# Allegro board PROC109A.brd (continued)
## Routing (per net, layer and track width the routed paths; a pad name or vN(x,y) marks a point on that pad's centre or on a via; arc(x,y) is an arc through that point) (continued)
TEST_LED4_GREEN: length 184.3
  TOP w0.102: v2(79.85,-47.86) 79.81,-47.81 U18.F3
  L03_SIG1 w0.121: v1(169.57,-12.28) 172.4,-12.28 173.27,-13.14 173.27,-15.1 170.87,-17.5 168.45,-17.5 157.63,-28.32 157.63,-52.83 157.8,-53 157.8,-55.25 156.21,-56.85 144.72,-56.85 142.85,-58.71 140.17,-58.71 138.28,-56.82 132.26,-56.82 131.44,-56 125.55,-56 125.16,-56.39 116.02,-56.39 115.95,-56.33 v1(115.87,-56.33) 115.56,-56.01 106.65,-56.01 106.61,-55.98 97.99,-55.98 96.83,-57.15 89.21,-57.15 89.04,-57.31 81.98,-57.31 81.33,-56.67 79.76,-56.67 78.89,-55.8 78.89,-51.89 79.04,-51.74 79.04,-48.66 v2(79.85,-47.86)
  BOTTOM w0.135: v1(115.87,-56.33) 115.87,-55.63 114.35,-54.1 114.35,-36.7 111.76,-34.11 111.76,-25.98 111.76,-25.96 111.77,-25.94 112.29,-25.43 113.67,-25.43 114.68,-24.41 U51.11 ; Q4.3 170.24,-12.51 170.02,-12.28 v1(169.57,-12.28) 168.77,-12.28 R165.2
TIMER_IO0: length 91.3
  TOP w0.102: v2(81.84,-40.35) 81.81,-40.32 U18.K18
  L03_SIG1 w0.121: v1(79.91,-26.54) 82.35,-28.98 82.35,-35.44 82.01,-35.78 82.01,-40.18 v2(81.84,-40.35) ; v1(91.1,-24.95) 91.08,-24.95 90.96,-24.83 90.96,-24.82 90.93,-24.79 90.93,-24.51 91.64,-23.8 93.83,-23.8 94.39,-24.36 94.95,-24.36 95.3,-24 95.99,-24 96.1,-24.11 96.45,-24.11 96.56,-24 v1(101.27,-24)
  BOTTOM w0.135: v1(101.27,-24) 101.35,-24.08 101.35,-24.51 102.54,-25.71 102.54,-27.05 103.11,-27.62 103.36,-27.62 103.78,-28.04 103.78,-28.73 97.38,-35.13 97.38,-36.81 96.77,-37.41 94.35,-37.41 93.66,-38.11 93.66,-39.91 94.12,-40.37 95.38,-41.63 95.38,-51.57 95.81,-52 95.81,-59.32 95.93,-59.45 95.93,-60.76 94.61,-62.08 92.13,-62.08 91.42,-61.38 U50.12 ; 90.1,-25.33 R193.1 ; 90.1,-25.33 88.3,-25.33 87.93,-24.97 87.58,-24.97 86.56,-23.95 82.5,-23.95 v1(79.91,-26.54) ; 90.1,-25.33 90.72,-25.33 v1(91.1,-24.95)
TIMER_IO0/EHPWM3_B: length 56.4
  TOP w0.135: v1(101.19,-19.15) 102.31,-18.03 J6.1
  BOTTOM w0.135: v1(101.19,-19.15) 100.8,-19.54 100.8,-24.35 102.04,-25.59 102.04,-26.93 103,-27.89 103.25,-27.89 103.5,-28.14 103.5,-28.63 97.43,-34.7 96.08,-34.7 93.12,-37.66 93.12,-40.14 94.81,-41.82 94.81,-51.76 95.25,-52.21 95.25,-59.53 95.39,-59.67 95.39,-60.33 94.35,-61.38 92.39,-61.38 92.22,-61.22 U50.10
TIMER_IO1: length 55.9
  TOP w0.102: 81.36,-37.97 81.39,-38 81.39,-39.03 81.39,-39.04 U18.K20
  TOP w0.135: v1(78.71,-28.68) 81.74,-31.7 81.74,-34.01 80.95,-34.8 80.95,-35.36 81.36,-35.77 81.36,-37.97 ; R19.1 89.51,-23.47 v1(89.51,-22.4)
  L03_SIG1 w0.121: v1(108.89,-20.83) 107.57,-22.15 102.83,-22.15 102.02,-22.96 101.67,-22.96 100.86,-22.15 97.15,-22.15 97.13,-22.13 95.97,-22.13 95.95,-22.15 93.29,-22.15 92.62,-22.83 89.93,-22.83 v1(89.51,-22.4)
  BOTTOM w0.135: v1(89.51,-22.4) 89.42,-22.31 82.72,-22.31 78.05,-26.97 78.05,-28.02 v1(78.71,-28.68) ; U51.16 113.68,-21.78 113.05,-21.15 109.21,-21.15 v1(108.89,-20.83)
TIMER_IO1/EHPWM5_A: length 11.3
  BOTTOM w0.135: J6.3 106.79,-19.22 106.79,-19.23 106.79,-19.39 107.44,-20.04 107.44,-20.32 107.76,-20.63 108.09,-20.63 108.6,-20.13 109.18,-20.13 109.39,-20.34 113.41,-20.34 114.68,-21.61 U51.2
TIMER_IO2: length 61.8
  TOP w0.102: v2(81.46,-39.76) 81.4,-39.82 U18.J19
  TOP w0.135: v1(107.87,-20.14) 107.87,-20.59 107.43,-21.03 106.65,-21.03 106.17,-20.55 101.22,-20.55 100.86,-20.9 100.86,-20.93 100.53,-21.26 92.1,-21.26 91.76,-21.6 91.76,-25.44 v1(92.08,-25.76)
  L03_SIG1 w0.121: v2(81.46,-39.76) 81.75,-39.47 81.75,-35.68 82.09,-35.34 82.09,-29.31 79.93,-27.15 v1(78.92,-27.15)
  BOTTOM w0.135: R192.1 92.1,-25.25 92.08,-25.27 v1(92.08,-25.76) 88.34,-25.76 87.83,-25.25 87.48,-25.25 87.31,-25.08 86.49,-24.26 83.08,-24.26 80.19,-27.15 v1(78.92,-27.15) ; U51.3 115.08,-21.46 113.69,-20.07 109.5,-20.07 109.29,-19.86 108.16,-19.86 v1(107.87,-20.14)
TIMER_IO2/EHPWM8_B: length 10
  BOTTOM w0.135: U51.5 116.08,-20.58 115.23,-19.73 110.32,-19.73 110.18,-19.59 110.18,-18.89 J6.5
TIMER_IO3: length 70.4
  TOP w0.102: v2(80.33,-39.78) 80.59,-40.03 80.61,-40.03 U18.J18
  L03_SIG1 w0.102: v2(80.33,-39.78) 80.33,-38.15 80.51,-37.97
  L03_SIG1 w0.121: v1(116.54,-19.94) 116.23,-19.94 116.13,-19.84 110.82,-19.84 108.25,-22.41 102.94,-22.41 102.13,-23.21 101.57,-23.21 101.17,-22.82 99.69,-22.82 99.49,-23.01 95.57,-23.01 95.01,-23.57 94.34,-23.57 v1(93.45,-22.68) ; 80.51,-37.97 80.51,-35.88 80.41,-35.78 80.41,-34.58 81.07,-33.92 81.07,-33.39 79.98,-32.31 78.61,-32.31 78.16,-31.85 78.16,-29.64 78.56,-29.24 79.45,-29.24 79.78,-28.91 v1(79.78,-28.12)
  BOTTOM w0.135: 86.06,-22.83 v1(87.27,-24.05) 87.92,-24.7 88.05,-24.7 R194.1 ; 86.06,-22.83 87.22,-22.83 87.48,-22.58 89.08,-22.58 89.54,-23.04 93.09,-23.04 v1(93.45,-22.68) ; 86.06,-22.83 82.63,-22.83 78.49,-26.97 78.49,-27.56 79.04,-28.12 v1(79.78,-28.12) ; U51.9 115.48,-23.99 115.78,-24.28 116.53,-24.28 116.77,-24.05 116.95,-24.05 117.2,-23.8 117.2,-23.42 117.07,-23.29 117.07,-20.47 v1(116.54,-19.94)
TIMER_IO3/EHPWM8_A: length 9.8
  BOTTOM w0.135: U51.7 116.42,-23.19 116.45,-23.16 116.69,-23.16 116.79,-23.06 116.79,-20.8 115.44,-19.46 112.08,-19.46 111.87,-19.24 J6.7
TIMER_IO4: length 29
  TOP w0.135: v1(90.93,-21.62) 90.94,-21.62 R20.1
  L03_SIG1 w0.121: v1(105.66,-20.98) 105.22,-20.98 105.15,-21.06 103.17,-21.06 102.62,-21.62 102.25,-21.62 102.23,-21.6 101.46,-21.6 101.45,-21.62 v1(90.93,-21.62)
  BOTTOM w0.135: U51.12 114.28,-24.3 113.64,-24.94 111.24,-24.94 110.52,-24.23 110.52,-22.06 110.13,-21.67 106.35,-21.67 v1(105.66,-20.98)
TIMER_IO4/EHPWM7_B: length 11.1
  BOTTOM w0.135: U51.10 115.08,-24.45 115.22,-24.59 116.64,-24.59 116.75,-24.45 116.88,-24.32 117.06,-24.32 117.59,-23.79 117.59,-20.38 116.46,-19.25 115.62,-19.25 J6.9
TIMER_IO4_R: length 30.5
  TOP w0.102: U18.J20 81.17,-39.04 81.17,-38.43 81,-38.25 81,-37.97
  TOP w0.135: 81,-37.97 81,-35.84 80.68,-35.52 80.68,-34.66 81.47,-33.87 81.47,-32.08 v1(79.04,-29.66) ; v1(86.28,-24.82) 86.28,-24.23 86.94,-23.57 87.55,-23.57 88.82,-24.84 90.32,-24.84 90.9,-24.26 R20.2
  BOTTOM w0.135: v1(79.04,-29.66) 85.56,-29.66 86.11,-29.11 86.11,-27.7 85.19,-26.79 85.19,-25.07 85.45,-24.82 v1(86.28,-24.82)
TIMER_IO5: length 118.4
  TOP w0.102: 80.7,-37.97 80.7,-38.56 80.7,-38.62 U18.J21
  TOP w0.135: v1(92.43,-22.4) 92.43,-23.47 R21.1 ; v1(77.19,-27.94) 77.19,-28.45 79.25,-30.51 79.48,-30.51 81.15,-32.18 81.15,-33.73 80.41,-34.47 80.41,-35.78 80.7,-36.07 80.7,-37.97
  L03_SIG1 w0.121: v1(120.52,-20.17) 119.87,-19.52 118.62,-19.52 118.41,-19.73 118.06,-19.73 117.85,-19.52 110.63,-19.52 109.6,-20.55 109.21,-20.55 109.07,-20.4 108.37,-20.4 106.88,-21.89 97.25,-21.89 97.23,-21.88 92.95,-21.88 v1(92.43,-22.4)
  BOTTOM w0.135: v1(92.43,-22.4) 90.96,-22.4 90.24,-21.69 89.8,-21.69 89.51,-21.97 82.62,-21.97 77.19,-27.41 v1(77.19,-27.94) ; v1(120.52,-20.17) 120.84,-20.48 120.84,-20.87 ; 120.85,-20.85 120.84,-20.87 ; 120.84,-20.87 120.53,-21.17 120.53,-23.3 120.62,-23.39 120.62,-26.76 120.76,-26.9 122.5,-26.9 122.76,-27.15 122.76,-27.63 125.56,-30.44 129.58,-30.44 130.31,-31.17 130.31,-38.24 130.31,-40.89 129.84,-41.36 129.84,-50.53 124.41,-55.96 119.96,-55.96 119.48,-55.47 117.86,-55.47 117.51,-55.13 117.51,-54.8 v1(117.2,-54.48) 117.2,-54.17 117.6,-53.77 117.8,-53.77 118.09,-53.47 U52.16
TIMER_IO5/EHPWM7_A: length 50.3
  TOP w0.135: J6.11 116.95,-19.24 117.44,-19.74 121.03,-19.74 123.38,-22.09 123.38,-27.7 120.42,-30.66 120.42,-32.59 120.67,-32.84 121.04,-32.84 122.87,-34.67 124.2,-34.67 125.93,-36.4 125.94,-36.41 125.94,-36.43 125.94,-36.97 125.94,-36.99 125.93,-37.01 125.67,-37.26 125.67,-38.42 125.35,-38.76 125.35,-40.56 125.29,-40.62 124.84,-41.07 124.84,-45.43 124.28,-45.99 124.28,-48.77 123.01,-50.04 121.39,-50.04 119.04,-52.39 v1(117.06,-52.39)
  BOTTOM w0.135: U52.2 117.17,-52.27 v1(117.06,-52.39)
TM4C129_TCK: length 5.1
  TOP w0.135: v1(24.43,-33.96) 24.53,-34.06 TP18.1
  BOTTOM w0.135: U37.100 21.9,-32.34 23.53,-33.96 v1(24.43,-33.96)
TM4C129_TDI: length 3.8
  TOP w0.135: TP16.1 21.77,-34.78 v1(21.77,-33.96)
  BOTTOM w0.135: U37.98 21.1,-33.3 v1(21.77,-33.96)
TM4C129_TDO: length 3.6
  TOP w0.135: v1(20.62,-32.97) 20.42,-33.18 TP15.1
  BOTTOM w0.135: U37.97 20.7,-32.89 v1(20.62,-32.97)
TM4C129_TMS: length 4.2
  TOP w0.135: TP17.1 23.16,-34.36 v1(22.91,-34.11)
  BOTTOM w0.135: v1(22.91,-34.11) 21.5,-32.7 U37.99
TUSB_ADDR: length 3.9
  TOP w0.135: U20.5 13.55,-46.09 13.87,-45.77 TP29.1
TUSB_ID: length 3.9
  TOP w0.135: TP28.1 9.02,-44.88 9.64,-44.88 10.45,-45.69 U20.9
TUSB_INT_N: length 2
  TOP w0.135: R110.1 14.14,-45 13.45,-45.69 U20.6
TUSB_OUT1: length 5.6
  TOP w0.135: R107.1 13.79,-42.11 13.26,-41.58 12.83,-41.58 12.27,-41.02 12.27,-39.42 12.57,-39.12 U15.2
TUSB_OUT1_R: length 3.5
  TOP w0.135: R107.2 R106.1 12.34,-44.3 11.92,-44.72 U20.7
TUSB_OUT2: length 7.3
  TOP w0.135: U15.1 12.63,-38.62 12.37,-38.35 R92.2 11.67,-39.97 9.45,-42.19 R104.1
TUSB_OUT2_R: length 3.6
  TOP w0.135: R104.2 R105.1 10.9,-44.39 11.52,-45.01 U20.8
TYPEC_CC1: length 15
  TOP w0.135: v1(13.46,-54.08) 11.52,-52.14 U20.1
  TOP w0.254: v1(17.78,-56.01) 17.77,-56.02 J10.A5
  L03_SIG1 w0.127: v1(13.46,-54.08) 13.46,-54.99 15.04,-56.57 17.22,-56.57 v1(17.78,-56.01)
TYPEC_CC2: length 18.9
  TOP w0.135: v1(13.51,-52.96) 11.92,-51.37 U20.2
  L03_SIG1 w0.127: J10.B5 18.46,-59.79 16.13,-59.79 12.55,-56.21 12.55,-53.92 v1(13.51,-52.96)
TYPEC_DN: length 15.3
  TOP w0.107: J10.A7 18.77,-56.16 18.64,-56.03 18.64,-55.48 v1(19,-55.12)
  L03_SIG1 w0.102: J10.B7 18.4,-57.95 18.4,-57.72 20.17,-55.95 20.17,-54.48 19.38,-53.7 18.9,-53.7 18.57,-54.03 18.57,-55.32 18.67,-55.42 18.88,-55.42 19,-55.3 v1(19,-55.12)
  BOTTOM w0.107: v1(19,-55.12) 18.7,-54.81 18.7,-54.59 18.09,-53.98 18.09,-53.64 18.32,-53.41 D6.1 18.32,-52.92 18.09,-52.69 18.09,-52.2 18.4,-51.89 L3.2
TYPEC_DP: length 15.3
  TOP w0.107: J10.A6 18.27,-56.16 18.4,-56.03 18.4,-55.46 v1(18.06,-55.12)
  L03_SIG1 w0.102: J10.B6 18.66,-57.97 18.66,-57.82 20.42,-56.06 20.42,-54.38 19.49,-53.44 18.8,-53.44 18.31,-53.92 18.31,-54.87 v1(18.06,-55.12)
  BOTTOM w0.107: L3.3 17.55,-51.89 17.85,-52.2 17.85,-52.69 17.62,-52.92 D7.1 17.62,-53.41 17.85,-53.64 17.85,-54.07 18.4,-54.62 18.4,-54.78 v1(18.06,-55.12)
UART0_HDR_CTS#: length 55.2
  TOP w0.135: U8.6 109.28,-25.5 v1(109.93,-24.85)
  L03_SIG1 w0.121: v1(109.93,-24.85) 112.26,-24.85 115.34,-21.76 115.58,-21.76 115.83,-21.52 119.83,-21.52 119.93,-21.62 125.45,-21.62 126.14,-22.32 127.15,-22.32 127.95,-21.52 133.5,-21.52 133.86,-21.16 136.78,-21.16 139.67,-18.26 153.52,-18.26 J17.2
UART0_HDR_RTS#: length 51.2
  TOP w0.135: v1(107.57,-23.85) 106.73,-23.85 103.13,-27.45 U8.12
  L03_SIG1 w0.121: J17.6 141.4,-14.33 137.38,-18.35 135.5,-18.35 133.09,-20.75 127.63,-20.75 127.58,-20.8 120.85,-20.8 120.8,-20.85 120.24,-20.85 120.15,-20.75 115.51,-20.75 115.27,-21 114.7,-21 114.56,-20.85 110.56,-20.85 v1(107.57,-23.85)
UART0_HDR_RXD: length 52.9
  TOP w0.135: v1(109.93,-26.97) 109.46,-27.45 U8.3
  L03_SIG1 w0.121: J17.5 148.33,-15.84 141.11,-15.84 138.05,-18.9 135.31,-18.9 133.2,-21.01 127.74,-21.01 127.69,-21.06 120.96,-21.06 120.91,-21.1 120.14,-21.1 120.04,-21.01 115.62,-21.01 115.37,-21.25 114.6,-21.25 114.45,-21.11 110.67,-21.11 108.25,-23.53 108.25,-26.31 108.92,-26.97 v1(109.93,-26.97)
UART0_HDR_TXD: length 55.6
  TOP w0.135: v1(109.32,-23.22) 105.94,-23.22 103.66,-25.5 U8.9
  L03_SIG1 w0.121: v1(109.32,-23.22) 109.63,-22.9 109.63,-22.57 110.84,-21.37 114.35,-21.37 114.49,-21.51 115.48,-21.51 115.72,-21.26 119.94,-21.26 120.03,-21.36 121.02,-21.36 121.04,-21.34 127.77,-21.34 127.84,-21.26 133.39,-21.26 133.75,-20.9 136.67,-20.9 141,-16.58 150.13,-16.58 J17.4
UART1_HDR_CTS#: length 57.8
  TOP w0.135: U12.6 114.27,-32.36 v1(114.27,-32.36)
  L03_SIG1 w0.121: J13.2 155.09,-23.04 136.71,-23.04 135.91,-22.24 134.21,-22.24 133.88,-22.58 128.33,-22.58 127.57,-23.34 125.53,-23.34 124.89,-22.7 120.77,-22.7 115.77,-27.7 115.77,-30.49 114.27,-31.99 v1(114.27,-32.36)
UART1_HDR_RTS#: length 52.8
  TOP w0.135: v1(107.49,-30.68) 106.6,-30.68 102.98,-34.3 U12.12
  L03_SIG1 w0.121: J13.6 142.67,-20.68 141.07,-22.27 137.26,-22.27 136.4,-21.41 133.96,-21.41 133.6,-21.77 128.06,-21.77 127.26,-22.57 126.04,-22.57 125.34,-21.88 115.83,-21.88 115.69,-22.02 115.62,-22.02 107.49,-30.15 v1(107.49,-30.68)
UART1_HDR_RXD: length 54.1
  TOP w0.135: U12.3 106.06,-34.3 105.56,-33.81 105.56,-32.26 106.64,-31.18 108.14,-31.18 v1(108.64,-30.68)
  L03_SIG1 w0.121: J13.5 148.67,-21.84 145.34,-21.84 145.3,-21.8 142.1,-21.8 141.38,-22.53 137.14,-22.53 136.32,-21.72 134.02,-21.72 133.71,-22.03 128.16,-22.03 127.36,-22.83 125.93,-22.83 125.24,-22.13 117.15,-22.13 108.95,-30.33 108.95,-30.37 v1(108.64,-30.68)
UART1_HDR_TXD: length 57.8
  TOP w0.135: U12.9 103.18,-32.36 105.41,-30.12 109.22,-30.12 v1(109.78,-30.68)
  L03_SIG1 w0.121: J13.4 150.27,-22.79 136.96,-22.79 136.16,-21.99 134.11,-21.99 133.77,-22.33 128.23,-22.33 127.47,-23.08 125.83,-23.08 125.13,-22.39 117.38,-22.39 115.87,-23.9 115.87,-24.16 115.03,-24.99 114.65,-24.99 109.78,-29.86 v1(109.78,-30.68)
USB0_DN: length 133.3
  TOP w0.107: v1(95.19,-38.63) 95.19,-38.62 94.83,-38.62 94.49,-38.97 92.12,-38.97 92.02,-39.07 91.84,-39.07 91.47,-39.45 89.48,-39.45 87.98,-40.95 87.27,-40.95 87.13,-40.82 U18.AA17
  BOTTOM w0.107: 95.21,-38.64 v1(95.19,-38.63) 95.46,-39.02 95.84,-39.02 96.26,-39.44 96.26,-51.52 96.47,-51.73 96.47,-59.05 96.59,-59.17 96.59,-61.85 95.24,-63.2 94.97,-63.2 94.95,-63.2 91.53,-63.2 91.34,-63.02 87.2,-63.02 84.17,-59.99 78.8,-59.99 75.85,-62.95 67.53,-62.95 66.83,-63.65 40.03,-63.65 40.02,-63.65 40.01,-63.65 39.99,-63.64 39.99,-63.63 38.91,-62.55 38.9,-62.55 38.89,-62.53 38.89,-62.52 38.89,-62.51 38.89,-55.6 38.89,-55.59 38.89,-55.58 38.9,-55.56 38.91,-55.56 40.51,-53.95 40.51,-50.54 39.44,-49.47 36.76,-49.47 36.75,-49.47 36.71,-49.47 35.49,-49.47 35.48,-49.47 35.44,-49.47 34.14,-49.47 34.14,-49.47 34.1,-49.47 32.87,-49.47 32.87,-49.47 32.83,-49.47 31.84,-49.47 31.83,-49.47 31.8,-49.47 31.78,-49.47 31.77,-49.47 30.71,-49.47 29.73,-50.46 29.72,-50.46 29.71,-50.47 29.7,-50.47 29.69,-50.47 22,-50.47 19.56,-48.04 18.28,-48.04 18.09,-48.23 18.09,-48.54 18.4,-48.85 L3.1
USB0_DP: length 133.5
  TOP w0.107: U18.AA16 87.13,-41.32 87.27,-41.18 88.08,-41.18 89.58,-39.68 90.33,-39.68 90.44,-39.79 90.44,-39.95 90.54,-40.06 90.76,-40.06 90.86,-39.95 90.86,-39.79 90.97,-39.68 91.56,-39.68 91.94,-39.3 92.12,-39.3 92.22,-39.2 94.52,-39.2 94.54,-39.2 94.86,-39.52 95.01,-39.52 v1(95.01,-39.52)
  BOTTOM w0.107: 95.14,-39.4 95.01,-39.52 v1(95.01,-39.52) 95.41,-39.26 95.74,-39.26 96.02,-39.54 96.02,-51.62 96.23,-51.83 96.23,-59.15 96.36,-59.27 96.36,-61.75 95.14,-62.97 94.96,-62.97 94.95,-62.97 91.63,-62.97 91.44,-62.78 87.29,-62.78 84.27,-59.75 78.71,-59.75 75.75,-62.71 67.44,-62.71 66.73,-63.42 40.1,-63.42 39.12,-62.44 39.12,-55.67 40.74,-54.05 40.74,-50.44 39.54,-49.24 36.78,-49.24 36.78,-49.24 36.71,-49.24 35.51,-49.24 35.51,-49.24 35.44,-49.24 34.16,-49.24 34.16,-49.24 34.09,-49.24 32.89,-49.24 32.86,-49.24 32.82,-49.24 31.85,-49.24 31.8,-49.23 31.76,-49.24 30.62,-49.24 29.62,-50.24 22.1,-50.24 19.66,-47.8 18.19,-47.8 17.85,-48.14 17.85,-48.54 17.55,-48.85 L3.4
USB0_DRVVBUS: length 7
  TOP w0.102: U18.B19 76.34,-39.82 76.16,-39.64
  TOP w0.135: TP21.1 72.65,-38.81 73.96,-38.81 74.29,-38.48 75,-38.48 76.16,-39.64
USB0_ID: length 14.9
  TOP w0.102: 87.74,-40.29 87.49,-40.54 86.67,-40.54 U18.Y17
  TOP w0.135: 87.74,-40.29 90,-38.02 91.92,-38.02 92.25,-38.35 93.52,-38.35 94.03,-37.85 97.36,-37.85 98.63,-36.58 R83.2
USB0_RCALIB: length 2.6
  TOP w0.102: U18.W17 85.89,-40.37 v2(85.93,-40.35)
  BOTTOM w0.135: v2(85.93,-40.35) 86.44,-39.84 86.44,-39.2 86.97,-38.67 R239.1
USB0_VBUS: length 155.3
  TOP w0.102: v2(85.93,-39.78) U18.V18
  TOP w0.381: R118.2 39.27,-47.88 R116.2 v1(39.27,-48.67)
  L03_SIG1 w0.254: v1(101.42,-15.54) 101.42,-15.04 100.56,-14.17 85.48,-14.17 83.32,-16.33 78.51,-16.33 75.02,-12.84 v1(38.98,-12.84) ; v1(103,-33.27) 101.22,-35.05 98.93,-35.05 98.76,-34.87 90.4,-34.87 85.93,-39.35 v2(85.93,-39.78)
  BOTTOM w0.254: v1(101.42,-15.54) 102.62,-16.74 102.62,-21.51 103.64,-22.53 106.95,-22.53 108.06,-23.65 108.06,-28.21 v1(103,-33.27) ; v1(38.98,-12.84) 38.15,-13.67 38.15,-20.37 40.01,-22.22 40.01,-23.75 35.55,-28.21 35.55,-30.34 39.88,-34.67 40.57,-34.67 41.1,-35.21 41.1,-46.83 v1(39.27,-48.67)
USBC_SHIELD:
  vias: v1(13.34,-61.09) v1(13.34,-62.36) v1(14.61,-61.09) v1(14.61,-62.36) v1(15.88,-61.09) v1(15.88,-62.36) v1(22.99,-61.09) v1(22.99,-62.36) v1(24.26,-61.09) v1(24.26,-62.36) v1(25.53,-62.36) v1(26.8,-62.36)
USER_INTN: length 28.7
  TOP w0.102: 76.05,-45.01 76.16,-45.01 76.23,-44.94 76.25,-44.94 76.31,-44.88 76.33,-44.88 76.67,-44.54 77.11,-44.54 U18.B9
  TOP w0.135: v1(62.08,-35.97) 62.15,-35.89 62.15,-34.54 TP12.1 60.46,-33.86 60.26,-33.66 U13.5 ; v1(63.98,-44.54) 65.6,-44.54 67.13,-46.08 68.83,-46.08 68.94,-45.97 69.01,-45.9 69.02,-45.89 70.85,-45.89 70.97,-45.77 73.76,-45.77 74.52,-45.01 76.05,-45.01
  BOTTOM w0.135: v1(62.08,-35.97) 63.98,-37.87 v1(63.98,-44.54)
VMON_MRN: length 21.1
  TOP w0.135: SW1.3 15.17,-12 15.05,-11.88 15.05,-11.87 14.43,-11.25 12.4,-11.25 11.65,-12 SW1.1 v1(10.44,-13.05)
  BOTTOM w0.135: U27.1 15.74,-17.8 14.63,-16.69 14.63,-15.34 14.27,-14.99 Q8.2 Q8.1 12.72,-14.34 Q8.8 12.07,-14.34 Q8.6 ; Q8.6 10.97,-14.34 10.44,-13.8 v1(10.44,-13.05) ; Q8.6 Q8.5
  BOTTOM w0.152: v1(10.44,-13.05) 10.44,-12.34 C79.1 9.81,-12.32 9.75,-12.26 D5.1 R171.1
VMON_VSYS: length 28.8
  TOP w0.102: U18.G13 79.46,-42.82 v2(79.42,-42.77)
  L03_SIG1 w0.102: 77.29,-41.65 77.48,-41.65 77.71,-41.42 78.59,-41.42 78.87,-41.7 78.87,-42.22 v2(79.42,-42.77)
  L03_SIG1 w0.203: v1(66.57,-40.44) 67.76,-41.62 67.76,-43.48 68.21,-43.92 69.33,-43.92 70.89,-42.37 73.89,-42.37 74.6,-41.66 77.28,-41.66 77.29,-41.65
  BOTTOM w0.203: C232.1 64.74,-42.27 v1(66.57,-40.44)
  BOTTOM w0.33: R255.1 64.58,-47.86 C232.1
  BOTTOM w0.508: R262.2 R255.1
VPP_1V8: length 28.5
  TOP w0.203: U14.5 54,-35.41 54,-35.41
  TOP w0.254: 54.86,-35.76 C38.1 57.15,-35.76 58.75,-37.36 v1(58.75,-38) ; 54.86,-35.76 54.2,-35.76 U14.5 ; 54.86,-35.76 54.86,-35.76
  TOP w0.33: U18.E16 78.89,-40.86 v2(78.9,-40.86)
  L03_SIG1 w0.254: v1(58.75,-38) 62.36,-38 64.29,-39.93 69.01,-39.93 69.37,-40.28 73.05,-40.28 73.62,-40.86 v2(78.9,-40.86)
VPP_1V8_REG_EN: length 40.1
  TOP w0.135: v1(40.59,-40) 41.01,-40.42 41.01,-52.47 38.59,-54.88 38.59,-62.38 36.17,-64.8 J22.2
  TOP w0.33: U14.3 50.18,-37.86 49.6,-38.44 R90.2 v1(49.07,-39.19)
  L03_SIG1 w0.121: v1(40.59,-40) 48.26,-40 v1(49.07,-39.19)
VPP_1V8_REG_EN_ON: length 4.6
  TOP w0.135: R593.1 33.64,-61.91 32.46,-63.09 J22.1
VSYS_3V3: length 279.6
  TOP w0.135: R598.2 124.6,-50.38 124.74,-50.25 v1(124.74,-49.78)
  TOP w0.254: R5.2 v1(71.06,-16.48) ; U19.30 135.01,-45.39 134.51,-44.9 C54.1 133.98,-44.33 v1(133.99,-44.32) ; U13.8 58.76,-31.58 C29.1 ; v1(56.58,-29.16) 56.58,-31.63 54.1,-34.11 46.36,-34.11 45.54,-34.92 R80.1 ; v1(112.25,-22.3) 112.02,-22.53 C9.2 ; v1(112.25,-22.3) 112.25,-23.23 112.21,-23.27 U3.4 ; v1(112.25,-22.3) 112.22,-22.3 ; C41.1 63.93,-37.62 64.19,-37.36 64.19,-36.81 64.4,-36.59 R89.2 ; U5.6 58.41,-26.43 C15.1 58.03,-26.44 v1(57.85,-26.62) ; U7.30 135.01,-26.34 134.51,-25.85 C14.1 133.98,-25.34 v1(133.91,-25.27) ; U16.6 26.62,-40.03 v1(26.57,-39.98) ; v1(159.87,-50.14) C59.1 159.44,-49.53 159.06,-49.9 U22.10 ; U19.18 C46.1 C43.1 140.18,-38.35 v1(140.16,-38.33) ; U4.24 31.84,-21.95 32.13,-21.67 ; U7.18 C7.1 C6.1 140.18,-19.3 v1(140.16,-19.28) ; 33.5,-22.86 33.34,-23.02 U4.23 ; U16.3 C45.1 33.28,-40.03 v1(33.35,-40.11)
  TOP w0.305: C41.1 63.39,-37.87 U17.8 ; v1(50.78,-27.05) 51.03,-27.3 C21.1
  TOP w0.33: v1(34.77,-21.49) 34.87,-21.59 C8.1 ; C43.1 v1(139.54,-39.42) ; v1(52.05,-27.05) 51.92,-27.18 C22.1 ; v1(67.61,-59.49) 67.61,-59.38 67.95,-59.05 C74.1 68.33,-58.55 68.09,-58.31 U25.1 ; v1(126.83,-25.23) C13.1 C16.2 126.29,-26.67 126.19,-26.57 ; U2.2 82.27,-26.67 82.78,-26.16 82.78,-25.9 83.2,-25.48 C12.1 83.21,-24.32 C10.1 ; U12.14 C37.1 v1(99.84,-36.19) ; v1(115.95,-26.54) 115.95,-26.54 R32.2 ; C29.1 v1(58.17,-31.57) ; C6.1 v1(139.54,-20.37) ; R37.2 84.51,-25.72 v1(84.76,-25.48) ; U8.14 C24.1 v1(99.84,-29.31)
  TOP w0.381: v1(91.77,-36.22) 91.99,-36.22 92.61,-35.6 R590.2 ; R1.2 18.52,-14.61 v1(18.52,-14.6) ; R89.2 65.63,-36.59 66.6,-37.57 R88.1 ; R112.2 44.17,-39.27 v1(44.2,-39.24) ; v1(139.54,-39.42) 139.49,-39.36 R95.1 ; R10.2 84.24,-18.07 84.25,-18.06 v1(84.33,-18.06) ; v1(98.27,-32.59) 98.25,-32.59 97.57,-31.92 R588.2 ; v1(65.1,-66.24) 65.13,-66.24 65.43,-65.94 R164.2 ; R593.2 34.68,-60.71 35.71,-61.73 v1(35.71,-62.48) ; R3.2 34.28,-16.09 34.29,-16.08 v1(34.3,-16.08) ; v1(67.13,-35.99) 67.31,-36.17 R82.1 ; 126.19,-26.57 126.11,-26.49 U6.6 ; v1(69.55,-24.81) 69.03,-25.33 R36.2 ; R4.2 v1(25.58,-16.1) ; 10.59,-31.04 10.37,-30.82 U9.1
  TOP w0.508: v1(139.14,-62.2) 139.14,-61.24 v1(142.23,-58.15) ; R129.1 v1(132.21,-49.99) ; R89.2 64.94,-36.53 v1(64.94,-35.89) ; R45.2 97.34,-25.81 v1(97.33,-25.81) ; R135.1 140.19,-52.98 140.18,-52.98 140.18,-53.06 v1(140.18,-53.06) ; C40.1 R80.1 ; R39.2 87.13,-25.6 v1(86.99,-25.46) ; R68.1 v1(132.21,-30.94) ; 98.81,-58.67 96.73,-58.67 96.7,-58.64 93.78,-58.64 92.76,-59.66 v1(89.19,-59.66) ; 98.81,-58.67 98.81,-59.45 98.81,-59.48 98.83,-59.5 100.5,-61.18 R163.1 ; 98.81,-58.67 98.81,-58.16 99.23,-57.74 99.37,-57.74 v1(99.82,-57.29) ; C10.1 v1(83.23,-23.38) ; R44.2 95.81,-25.79 v1(95.81,-25.78) ; R40.2 89.16,-26.48 v1(89.3,-26.62) 89.43,-26.49 89.66,-26.49 89.67,-26.48 R41.2 ; v1(94.31,-25.78) 94.29,-25.8 R43.2 ; 49.64,-24.64 49.36,-24.91 R35.1 49.36,-27.03 49.64,-27.3 C27.1 ; R12.1 v1(135.95,-20.19) ; R73.1 136.22,-33.63 135.89,-33.96 v1(135.89,-33.97) ; R134.1 v1(136.22,-53.04) ; R79.1 v1(7.01,-33.91) ; R91.1 5.55,-37.32 5.18,-36.96 v1(5.16,-36.96) ; R136.1 141.66,-52.98 141.66,-52.98 v1(141.66,-53.06)
  L03_SIG1 w0.254: v1(68.38,-53.04) 68.02,-53.39 68.02,-53.5 67.61,-53.9 v1(67.61,-59.49)
  L04_PWR1 w0.508: v1(33.35,-40.11) 30.63,-40.11 ; v1(99.82,-57.29) 99.82,-55.17 99.46,-55.53 98.95,-55.53 98.59,-55.17 98.59,-54.66 98.95,-54.3 99.73,-54.3 99.82,-54.2 ; v1(67.61,-59.49) 66.45,-60.66 66.45,-62.18 65.61,-63.02
  L05_GND2 w0.508: v1(142.23,-58.15) 142.23,-55.06 v1(143.31,-53.97)
  BOTTOM w0.135: v1(124.74,-49.78) 124.59,-49.94 R599.2 ; U51.14 113.08,-23.19 113.06,-23.16 C272.2 ; U50.14 90.22,-60.04 90.15,-59.97 C271.2 89.43,-59.97 89.19,-59.72 v1(89.19,-59.66) ; v1(118.34,-54.31) C273.2 118.9,-53.87 118.89,-53.87 U52.14 ; 132.99,-28.8 v1(132.99,-28.78)
  BOTTOM w0.178: C259.1 U42.1
  BOTTOM w0.203: C122.1 120.88,-34.7 ; C218.1 120.88,-45.32 ; U33.5 122.15,-31.9 121.97,-31.72 ; C219.1 119.87,-45.32 ; U39.4 121.14,-43.39
  BOTTOM w0.254: U40.8 110.46,-44.84 110.58,-44.96 112.64,-44.96 v1(112.7,-44.91) ; v1(139.14,-62.2) C270.1 140.24,-62.2 140.24,-62.21 U46.2 ; U30.10 C90.1 96.96,-22.56 v1(96.95,-22.56) ; U32.15 C106.1 ; v1(111.17,-50.16) C248.1 110.92,-49.35 109.71,-49.35 U40.17 ; v1(115.95,-26.54) 115.95,-27.05 116.36,-27.46 C103.1 117.14,-27.64 117.88,-27.64 118.06,-27.46 U32.2 ; v1(112.25,-22.3) 112.19,-22.35 112.19,-22.96 112.39,-23.16 C272.2 ; U46.8 v1(142.23,-58.15) ; C93.1 133.99,-25.35 v1(133.91,-25.27) ; v1(92.15,-39.9) 92.02,-39.78 FB4.1 ; v1(111.55,-40.77) C166.1 U40.1 ; v1(103.64,-45.89) 103.63,-45.88 C209.1 104.4,-45.14 104.6,-45.34 U40.30
  BOTTOM w0.33: R236.2 142.1,-35.81 v1(142.88,-35.81) 142.88,-35.13 142.6,-34.85 C119.1 140.68,-34.85 140.35,-34.52 U34.5 ; C259.1 68.83,-53.37 68.5,-53.04 v1(68.38,-53.04) ; v1(140.16,-38.33) 140.21,-38.38 C152.1 ; C54.1 133.98,-44.33 v1(133.99,-44.32) ; C159.1 140.16,-39.16 C152.1 ; v1(168.05,-58.22) C265.2 166.15,-58.22 165.82,-57.89 U44.5 ; v1(139.54,-39.42) 139.85,-39.12 C152.1 ; v1(160.21,-32.11) 160.15,-32.11 160.15,-32.11 C112.2 159.13,-32.11 159.1,-32.13 ; U43.5 140.92,-53.75 C258.1 143.08,-53.75 v1(143.31,-53.97) 143.31,-54.58 143.06,-54.83 R275.2 ; v1(126.82,-29.74) 126.31,-29.23 C106.1 ; C86.1 C84.1 ; U31.5 C94.1 75.46,-26.75 v1(75.13,-26.42)
  BOTTOM w0.381: v1(45.58,-24.22) 43.64,-26.15 43.64,-32.28 43.3,-32.62 R224.2 ; v1(135.46,-33.2) 135.37,-33.28 R229.1 ; R258.1 v1(179.05,-39.07) ; v1(139.54,-20.37) 139.85,-20.07 C84.1 ; v1(144.02,-33.2) 143.94,-33.2 143.93,-33.21 R226.1 ; v1(142.47,-52.25) 142.48,-52.26 R266.1 ; R225.1 146.17,-33.21 v1(146.18,-33.2) ; R218.1 132.99,-28.8 ; R265.1 v1(145.51,-52.26) ; R264.1 v1(147.34,-52.26) ; R269.1 v1(133.94,-52.26) ; R210.1 v1(178.94,-18.42) ; R170.2 v1(27.61,-15.32) ; v1(133.99,-44.32) 132.13,-44.32 131.89,-44.57 131.89,-46.73 131.73,-46.89 131.73,-47.35 132.21,-47.83 v1(132.99,-47.83) 132.99,-47.86 R254.1 ; R268.1 v1(135.47,-52.26) ; R230.1 133.85,-33.28 v1(133.93,-33.2) ; R227.1 141.35,-33.21 U34.5 ; 159.1,-32.13 U35.1
  BOTTOM w0.508: v1(91.82,-38.58) 91.25,-39.15 FB4.1 ; R283.1 v1(174.48,-63.7) ; R257.2 v1(157,-42.75) ; R201.2 23.02,-24.23 23.6,-24.81 23.6,-26.75 22.83,-27.51 v1(21.67,-27.51) ; R285.1 v1(171.48,-63.7) ; v1(64.94,-35.89) 64.94,-36.16 65.45,-36.67 R238.1 R237.1 ; FB3.1 71.83,-36.27 v1(70.97,-35.41) ; R223.2 v1(161.34,-33.15) ; v1(44.2,-39.24) 44.2,-35.1 42.55,-33.45 R224.2 ; R169.1 R168.1 v1(175.9,-10.91) ; R220.2 v1(161.34,-36.24) ; R181.2 v1(75.16,-19.3) ; R252.2 v1(157,-46.05) ; R183.2 v1(79.78,-20.65) ; R167.1 166.56,-12.28 v1(166.55,-12.27) 166.54,-12.28 R166.1 ; R282.1 v1(175.98,-63.7) ; R284.1 v1(172.98,-63.7)
  vias: v1(9.63,-32.72) v1(10.49,-31.88) v1(33.5,-21.49) v1(36.98,-62.48) v1(50.78,-24.51) v1(50.78,-25.78) v1(52.05,-24.51) v1(52.05,-25.78) v1(53.32,-24.51) v1(53.32,-25.78) v1(53.32,-27.05) v1(54.59,-24.51) v1(54.59,-25.78) v1(54.59,-27.05) v1(56.58,-26.62) v1(56.58,-27.89) v1(57.85,-27.89) v1(57.85,-29.16) v1(59.12,-27.89) v1(59.12,-29.16) v1(88.87,-53.11) v1(89.51,-52.7) v1(99.09,-15.14) v1(100.36,-15.14) v1(100.36,-16.41) v1(116.59,-32.26) v1(116.59,-33.53) v1(116.59,-34.8) v1(116.59,-42.98) v1(116.59,-44.25) v1(116.59,-45.52) v1(117.86,-32.26) v1(117.86,-33.53) v1(117.86,-34.8) v1(117.86,-42.98) v1(117.86,-44.25) v1(117.86,-45.52)
VSYS_3V3_CT: length 2.7
  BOTTOM w0.254: C81.1 17.24,-15.97 U27.4
VSYS_3V3_FB: length 4.4
  TOP w0.254: U10.2 43.93,-32.07 43.92,-32.07 43.92,-33.51 R77.1 R80.2 C40.2
VSYS_3V3_R: length 3.9
  TOP w0.508: C26.1 47.6,-27.07 48.38,-26.29 R35.2 48.38,-24.78 48.11,-24.51
VSYS_3V3_SENSE: length 6.2
  BOTTOM w0.135: R195.1 R201.1 21.3,-24.19 20.35,-23.24 20.35,-21.64 19.8,-21.1 U27.9
VSYS_3V3_SW: length 4.8
  TOP w0.254: 44.85,-29.17 44.43,-29.59 U10.6
  TOP w0.762: 44.85,-29.17 L1.1
VSYS_5V0: length 100.5
  TOP w0.254: U10.7 43.93,-29.04 C25.1 ; U21.7 49.64,-44.28 C51.1 ; U23.8 32.7,-50.99 32.72,-50.98 ; U23.7 32.78,-51.49
  TOP w0.305: 122.6,-31.23 122.6,-31.38 122.45,-31.52 C123.1 121.72,-32.05 v1(121.36,-32.41)
  TOP w0.381: v1(34.54,-50.11) 34.97,-49.69 R117.1 ; R85.2 43.11,-36.13 v1(43.18,-36.19) ; R86.1 6.73,-35.94 8.64,-34.03 11.68,-34.03 12.7,-35.05 15.57,-35.05 17.11,-33.51 17.11,-25.78 v1(16.54,-25.2) ; R11.1 v1(12.05,-18.96)
  TOP w0.508: U14.1 50.36,-35.96 49.94,-35.53 ; v1(100.5,-59.48) R161.2 v1(99.69,-58.67)
  TOP w0.762: J9.1 137.27,-59.57 131.34,-53.64 129.08,-53.64 127.36,-51.92 127.36,-34.26 124.32,-31.23 122.6,-31.23
  BOTTOM w0.203: U33.4 121.62,-32.67 v1(121.36,-32.41)
  BOTTOM w0.254: U27.14 16.24,-23.62 16.38,-23.77 C91.1 16.38,-25.04 v1(16.54,-25.2) ; U46.15 146.26,-62.21 C269.1 v1(146.89,-62.2)
  BOTTOM w0.33: v1(163.42,-52.02) R270.1 v1(164.19,-51.21) ; v1(65.53,-51.43) 65.56,-51.4 R262.1
  BOTTOM w0.381: R188.1 23.2,-22.63 v1(23.27,-22.56) ; v1(12.05,-18.96) 9.28,-16.18 R171.2 ; v1(16.54,-25.2) 15.14,-26.59 13.64,-26.59 13.09,-27.15 12.36,-27.15 12.07,-27.43 R211.2
  BOTTOM w0.508: R273.1 v1(154.79,-53.95) ; R274.1 v1(152.98,-53.95) ; R280.1 v1(154.79,-60.3) ; R279.1 v1(156.51,-60.3) ; R272.1 v1(156.51,-53.95) ; R281.1 v1(152.98,-60.3)
  vias: v1(32.26,-50.09) v1(33.27,-50.11) v1(33.27,-51.08) v1(34.54,-51.08) v1(35.89,-50.11) v1(35.89,-51.08) v1(35.92,-52.02) v1(37.16,-50.11) v1(37.16,-51.08) v1(37.19,-52.02) v1(39.98,-26.03) v1(39.98,-27.3) v1(39.98,-28.57) v1(39.98,-29.84) v1(41.25,-26.03) v1(41.25,-27.3) v1(41.25,-28.57) v1(41.25,-29.84) v1(42.52,-26.03) v1(42.52,-27.3) v1(42.52,-28.57) v1(42.52,-29.84) v1(45.7,-41.33) v1(45.7,-42.6) v1(45.7,-43.87) v1(45.7,-45.14) v1(46.84,-37.64) v1(46.89,-35.1) v1(46.86,-36.19) v1(46.97,-41.33) v1(46.97,-42.6) v1(46.97,-43.87) v1(46.97,-45.14) v1(48.16,-35.1) v1(48.24,-41.33) v1(48.24,-42.6) v1(48.24,-43.87) v1(48.24,-45.14)
VSYS_5V0_CT: length 2.4
  TOP w0.203: U23.6 32.75,-51.99 33.02,-52.26 C69.1
VSYS_5V0_ON: length 33.6
  TOP w0.254: U23.3 29.06,-51.99 29.06,-51.99 29.01,-51.99 v1(28.93,-52.07) ; U15.4 16.27,-39.62 16.54,-39.88 LD9.1 v1(17.15,-40.5)
  L03_SIG1 w0.203: v1(17.15,-40.5) 15.94,-39.29 14.71,-39.29 13.87,-40.13 13.87,-47.02 14.73,-47.88 22.81,-47.88 23.39,-48.46 23.39,-51.38 24.08,-52.07 v1(28.93,-52.07)
VUSB_5V0: length 55.4
  TOP w0.135: v1(15.12,-47.22) 23.04,-47.22 24.21,-48.39
  TOP w0.178: 10.26,-46.89 U20.12
  TOP w0.254: U15.5 15.91,-38.62 16.07,-38.46 C42.1 ; U23.4 29.2,-52.49 29.07,-52.62 28.68,-52.62 28.42,-52.37 28.42,-51.54 ; U23.1 29.02,-50.99 ; v1(9.3,-46.25) 9.3,-46.3 C57.1 10.21,-46.84 10.26,-46.89 ; U23.2 29.04,-51.49 28.88,-51.33
  TOP w0.33: C42.1 16.56,-38.46 v1(17.27,-38.46) ; v1(14.63,-44.2) 14.79,-44.2 15.12,-44.53 R110.2
  TOP w0.381: v1(4.34,-47.88) 4.29,-47.93 v1(3.07,-47.93) v1(1.8,-47.93) ; v1(17.27,-38.46) 17.71,-38.9 R94.1 ; R106.2 R105.2 10.55,-42.74 v1(10.19,-43.1) ; R113.2 v1(15.12,-47.22)
  L03_SIG1 w0.508: v1(9.3,-46.25) 9.3,-43.99 v1(10.19,-43.1)
  L04_PWR1 w0.381: v1(10.19,-43.1) 10.19,-40.56 12.29,-38.46 v1(17.27,-38.46)
  L04_PWR1 w0.508: v1(4.34,-47.88) 7.67,-47.88 v1(9.3,-46.25)
  BOTTOM w0.33: C226.1 3.81,-47.37
  BOTTOM w0.381: v1(10.19,-43.1) 11.28,-44.2 v1(14.63,-44.2) 14.63,-46.73 v1(15.12,-47.22)
WDI: length 3.1
  TOP w0.135: R9.2 v1(13.84,-18.06)
  BOTTOM w0.135: v1(13.84,-18.06) 13.84,-19.47 13.97,-19.6 U27.20
WDO: length 2.3
  TOP w0.135: v1(13.49,-20.56) 13.09,-20.16 R11.2
  BOTTOM w0.135: v1(13.49,-20.56) 13.95,-20.1 U27.19
XDS110_DEBUG_ID4: length 3.7
  TOP w0.135: R98.1 v1(20.5,-44.17)
  BOTTOM w0.135: U37.63 21.1,-45.78 21.21,-45.67 21.21,-44.88 v1(20.5,-44.17)
XDS110_DEBUG_ID5: length 3.6
  TOP w0.135: R99.1 v1(22.05,-44.17)
  BOTTOM w0.135: v1(22.05,-44.17) 21.5,-44.71 U37.62
XDS110_DEBUG_ID6: length 4.3
  TOP w0.135: R100.1 v1(23.52,-44.17)
  BOTTOM w0.135: v1(23.52,-44.17) 23.07,-44.17 21.9,-45.34 U37.61
XDS110_DEBUG_ID7: length 5.3
  TOP w0.135: R101.1 v1(24.99,-44.17)
  BOTTOM w0.135: U37.60 22.3,-45.51 23.11,-44.7 24.46,-44.7 v1(24.99,-44.17)
XDS110_EMU0: length 7.8
  TOP w0.135: v1(29.84,-45.49) R109.1 29.26,-44.81 29.06,-44.61 29.06,-41.58 28.51,-41.03 U16.8
  BOTTOM w0.135: U37.42 29.5,-45.63 29.64,-45.49 v1(29.84,-45.49)
XDS110_EMU1: length 12.2
  TOP w0.135: U16.1 31.62,-41.03 32.03,-41.45 32.03,-45.64 31.5,-46.18 29.06,-46.18 v1(28.37,-45.49) R108.1
  BOTTOM w0.135: U37.43 29.1,-45.67 28.93,-45.49 v1(28.37,-45.49)
XDS110_PROG_STAZ1: length 35.2
  TOP w0.135: R114.2 v1(6.5,-47.09)
  L03_SIG1 w0.121: v1(6.5,-47.09) 7.16,-46.43 7.16,-44.68 16.18,-35.66 19.43,-35.66 20.29,-34.8 32.57,-34.8 v1(33.38,-33.99)
  BOTTOM w0.135: v1(33.38,-33.99) 34.6,-33.99 U37.4
XDS110_PROG_STAZ2: length 36.8
  TOP w0.135: v1(6.25,-44.09) 5.82,-44.52 R111.2
  L03_SIG1 w0.121: v1(35.83,-33.59) 35.74,-33.5 33.12,-33.5 32.09,-34.54 19.92,-34.54 19.05,-35.41 14.69,-35.41 8.61,-41.49 8.61,-41.73 v1(6.25,-44.09)
  BOTTOM w0.135: v1(35.83,-33.59) 35.82,-33.59 U37.3
XDS110_TCK: length 44.4
  TOP w0.135: U25.13 70.04,-50.76 v1(70.33,-50.47)
  L03_SIG1 w0.121: v1(70.33,-50.47) 69.91,-50.05 68.52,-50.05 67.23,-48.77 66.31,-48.77 64.62,-47.07 64.62,-46.27 62.22,-43.87 50.66,-43.87 48.9,-45.63 32.91,-45.63 v1(32.79,-45.52)
  BOTTOM w0.135: v1(32.79,-45.52) 32.56,-45.52 32.3,-45.77 U37.35
XDS110_TDI: length 49.3
  TOP w0.135: U25.12 v1(70.69,-53.67)
  L03_SIG1 w0.121: v1(70.69,-53.67) 70.69,-52.96 69.52,-51.79 68.97,-51.79 64.34,-47.15 64.34,-46.35 62.81,-44.82 50.18,-44.82 48.09,-46.91 39.29,-46.91 38.76,-46.38 31.65,-46.38 v1(30.76,-45.49)
  BOTTOM w0.135: v1(30.76,-45.49) 31.1,-45.84 U37.38
XDS110_TDO: length 50.4
  L03_SIG1 w0.121: v1(30.76,-44.58) 30,-44.58 29.18,-45.39 29.18,-48.13 29.59,-48.54 30.17,-48.54 30.45,-48.26 30.45,-47.73 31.16,-47.02 37.42,-47.02 38.39,-47.99 44.13,-47.99 45.04,-48.89 59.59,-48.89 60.78,-50.09 v1(60.78,-53.33)
  BOTTOM w0.135: U37.37 31.5,-45.32 v1(30.76,-44.58) ; v1(60.78,-53.33) 62.55,-53.33 63.32,-54.11 U42.7
XDS110_TMS: length 46.8
  TOP w0.135: v1(71.48,-50.44) 71.34,-50.58 U25.11
  L03_SIG1 w0.121: v1(71.48,-50.44) 70.74,-49.71 68.63,-49.71 67.34,-48.41 66.32,-48.41 64.87,-46.97 64.87,-46.16 62.33,-43.62 50.21,-43.62 49.28,-44.55 45.11,-44.55 44.28,-45.38 33.49,-45.38 v1(32.72,-44.6)
  BOTTOM w0.135: U37.36 31.9,-45.41 v1(32.72,-44.6)
XDS110_TRST#: length 53.3
  TOP w0.135: U25.10 71.99,-53.12 v1(72.01,-53.14)
  L03_SIG1 w0.121: v1(72.01,-53.14) 70.87,-54.28 69.91,-54.28 69.34,-53.71 69.34,-52.57 68.78,-52.01 68.77,-52 64.06,-47.29 64.06,-46.43 62.7,-45.08 50.58,-45.08 47.48,-48.18 44.82,-48.18 44.12,-47.48 38.31,-47.48 37.59,-46.76 30.48,-46.76 29.92,-47.32 v1(29.92,-48.03)
  BOTTOM w0.135: v1(29.92,-48.03) 30.3,-47.65 U37.40
XDS110_UART1_RXD: length 17.6
  L03_SIG1 w0.121: v1(39.65,-50.9) 39.65,-49.91 37.67,-47.93 v1(33.88,-47.93)
  BOTTOM w0.135: v1(39.65,-50.9) 39.65,-51.74 38.51,-52.88 34.57,-52.88 34.28,-53.17 U45.13 ; U37.33 33.1,-47.7 33.33,-47.93 v1(33.88,-47.93)
XDS110_UART1_TXD: length 17.6
  L03_SIG1 w0.121: v1(38.38,-50.83) 38.38,-49.2 37.57,-48.39 32.87,-48.39 v1(32.72,-48.23)
  BOTTOM w0.135: U45.11 32.98,-53.2 33.58,-52.6 37.74,-52.6 38.38,-51.97 v1(38.38,-50.83) ; v1(32.72,-48.23) 32.7,-48.22 U37.34
XDS110_VBUS_DET: length 21
  L03_SIG1 w0.121: v1(18.29,-28.98) 24.82,-28.98 v1(28.57,-32.74)
  BOTTOM w0.135: U37.1 33.58,-32.79 33.1,-33.27 29.11,-33.27 v1(28.57,-32.74)
  BOTTOM w0.508: R219.2 R212.1 17.58,-28.27 v1(18.29,-28.98)
XDS_RBIAS: length 2.6
  BOTTOM w0.178: R256.1 23.05,-48.96 23.05,-48.19 22.7,-47.84 U37.59
XDS_RESET#: length 6
  TOP w0.135: TP26.1 15.93,-41.25 v1(17.73,-41.25)
  BOTTOM w0.135: U37.70 18.12,-43.19 17.73,-42.8 v1(17.73,-41.25) R246.2
XDS_SHIELD:
  vias: v1(4.85,-58.62) v1(4.85,-59.89) v1(6.12,-58.62) v1(6.12,-59.89) v1(7.39,-58.62) v1(7.39,-59.89)
XDS_USB_D_N: length 35.3
  TOP w0.107: v1(10.4,-52.81) 10.06,-53.15 9.64,-53.15 9.5,-53.02 U24.7 U24.4 7.73,-53.02 7.59,-53.15 6.73,-53.15 6.52,-52.94 J20.2
  L03_SIG1 w0.102: v1(10.4,-52.81) 10.73,-53.14 11.27,-53.14 12.24,-52.17 12.24,-40.33 14.5,-38.07 15.85,-38.07 16.73,-37.19 17.22,-37.19 17.75,-36.65 18.36,-36.65 18.9,-37.19 20.47,-37.19 20.86,-36.79 20.86,-36 v1(20.52,-35.66)
  BOTTOM w0.107: v1(20.52,-35.66) 20.52,-35.86 20.63,-35.97 20.85,-35.97 20.96,-35.86 20.96,-34.44 20.42,-33.91 20.15,-33.91 20.07,-33.99 U37.93
XDS_USB_D_P: length 35.3
  TOP w0.107: J20.3 6.52,-53.59 6.73,-53.39 7.59,-53.39 7.73,-53.52 U24.5 U24.6 9.5,-53.52 9.64,-53.39 10.06,-53.39 v1(10.4,-53.73)
  L03_SIG1 w0.102: v1(21.46,-35.66) 21.12,-36 21.12,-36.89 20.57,-37.44 18.79,-37.44 18.26,-36.91 17.86,-36.91 17.33,-37.44 16.84,-37.44 15.95,-38.33 14.61,-38.33 12.5,-40.44 12.5,-52.27 11.37,-53.4 10.73,-53.4 v1(10.4,-53.73)
  BOTTOM w0.107: U37.94 20.02,-33.59 20.1,-33.68 20.52,-33.68 21.19,-34.35 21.19,-35.39 v1(21.46,-35.66)
XDS_USB_ID: length 32.3
  TOP w0.135: U24.9 v1(9.66,-52.02)
  TOP w0.178: v1(7.47,-52.37) 7.82,-52.02 U24.2 U24.9
  TOP w0.254: J20.4 v1(6.89,-54.24)
  L03_SIG1 w0.121: v1(14.25,-33.86) 14.25,-35.31 5.56,-43.99 5.56,-47.09 6.1,-47.62 7.87,-47.62 8.71,-48.46 8.71,-51.07 v1(9.66,-52.02)
  L03_SIG1 w0.127: v1(6.89,-54.24) 7.47,-53.67 v1(7.47,-52.37)
  BOTTOM w0.135: v1(14.25,-33.86) 14.7,-33.86 14.82,-33.73 R231.2
XDS_VREF: length 5.9
  BOTTOM w0.178: C129.1 36.63,-35.99 U37.9
  BOTTOM w0.33: C129.1 C128.1 38.1,-36.04
  BOTTOM w0.381: 38.1,-36.04 38.65,-36.04 R235.2 39.38,-35.8 39.64,-35.55 U36.3
N17247526: length 1.4
  TOP w0.135: LD15.2 v1(175.98,-66.24)
  BOTTOM w0.135: R282.2 v1(175.98,-66.24)
N17247539: length 1.4
  TOP w0.135: LD14.2 v1(174.48,-66.24)
  BOTTOM w0.135: R283.2 v1(174.48,-66.24)
N17247599: length 1.4
  TOP w0.135: LD13.2 v1(172.98,-66.24)
  BOTTOM w0.135: R284.2 v1(172.98,-66.24)
N17247637: length 1.4
  TOP w0.135: LD12.2 v1(171.48,-66.24)
  BOTTOM w0.135: R285.2 v1(171.48,-66.24)
N29126233: length 2.6
  TOP w0.135: SW4.11 24.16,-29.72 24.79,-30.35 R67.1
N29126235: length 2.5
  TOP w0.135: SW4.12 24.18,-28.45 24.59,-28.85 R53.1
N29126237: length 2.4
  TOP w0.135: SW4.13 24.41,-27.18 24.59,-27.36 R48.1
N29126239: length 2.3
  TOP w0.135: SW4.14 24.41,-25.91 24.46,-25.86 R34.1
N29126243: length 2.7
  TOP w0.135: SW4.10 24,-30.99 24.87,-31.85 R70.1
N29126245: length 2.4
  TOP w0.135: R28.1 24.74,-24.36 24.46,-24.64 SW4.15
N29126269: length 2.5
  TOP w0.135: R17.1 25.4,-22.9 24.93,-23.37 SW4.16
N30174920: length 3.2
  BOTTOM w0.135: U31.2 76.69,-21.75 76.56,-21.62 R180.2 R179.2
N30212600: length 7.4
  TOP w0.135: v1(163.84,-14.19) 164.78,-14.19 165.76,-13.21 LD2.1
  BOTTOM w0.135: Q5.2 Q5.1 ; Q5.1 v1(163.84,-14.19) ; Q5.1 163.84,-15.5 Q5.8 163.84,-16.15 Q5.6 Q5.5
N30212640: length 1.3
  TOP w0.135: LD1.2 167.34,-11.27 v1(167.34,-10.64)
  BOTTOM w0.135: R167.2 v1(167.34,-10.64)
N30212699: length 7
  TOP w0.135: LD1.1 167.32,-13.4 168.12,-14.19 v1(168.66,-14.19)
  BOTTOM w0.135: Q6.1 168.66,-15.5 Q6.8 168.66,-16.15 Q6.6 Q6.5 ; Q6.1 Q6.2 ; Q6.1 v1(168.66,-14.19)
N30213674: length 1.3
  TOP w0.135: v1(165.77,-10.63) 165.77,-11.26 LD2.2
  BOTTOM w0.135: v1(165.77,-10.63) 165.77,-11.28 R166.2
N30217069: length 3.6
  BOTTOM w0.178: U37.96 17.82,-32.79 17.57,-32.54 C114.1
  BOTTOM w0.33: R222.1 17.31,-31.95 17.1,-32.16 C114.1
N30217074: length 2.1
  BOTTOM w0.135: U37.95 17.85,-33.19 R231.1
N30217111: length 1.4
  TOP w0.135: LD10.2 R111.1
N30217160: length 1.4
  TOP w0.135: LD11.2 R114.1
N30310219: length 2.7
  TOP w0.381: D3.3 35.95,-46.38 R117.2 R118.1
N30339679: length 27.9
  TOP w0.135: U1.1 29.73,-16.09 30,-16.36 30,-17.32 27.46,-19.86 27.46,-20.47 26.29,-21.64 25.16,-21.64 24.73,-22.07 24,-22.07 22.84,-20.9 21.79,-20.9 20.4,-22.3 v1(14.71,-22.3) 13.82,-21.41 R15.1
  BOTTOM w0.135: v1(14.71,-22.3) 14.18,-22.3 13.84,-21.96 13.84,-20.85 14.1,-20.6 U27.18 ; v1(14.71,-22.3) 14.69,-22.28 U27.16 ; v1(14.71,-22.3) 15.05,-22.65 U27.15
N30360253: length 21.2
  TOP w0.135: U19.13 v1(142.68,-41.27) 142.68,-39.92 TP25.1 ; U19.48 142.68,-49.65 142.87,-49.84 v1(143.37,-49.84)
  BOTTOM w0.135: v1(143.37,-49.84) 141.25,-49.84 136.96,-45.54 136.96,-42.24 137.47,-41.73 141.71,-41.73 142.16,-41.27 v1(142.68,-41.27)
N30371240: length 3.5
  BOTTOM w0.135: J19.11 180.75,-39.07 R258.2
N30391563: length 2.3
  BOTTOM w0.135: R210.2 J18.11
N30391831: length 14
  TOP w0.135: U7.48 142.68,-30.69 142.8,-30.81 v1(143.33,-30.81) ; U7.13 v1(142.68,-22.22) 142.68,-20.87 TP4.1
  BOTTOM w0.135: v1(142.68,-22.22) 140.77,-24.14 140.77,-28.25 v1(143.33,-30.81)
N30573184: length 1.3
  TOP w0.135: R79.2 LD6.2
N30625746: length 12.9
  TOP w0.102: U18.B5 77.11,-47.09 76.55,-47.09 76.2,-47.44
  TOP w0.135: 76.2,-47.44 75.86,-47.78 75.86,-48.42 73.38,-50.9 73.38,-53.72 v1(72.36,-54.74)
  BOTTOM w0.135: R271.2 v1(72.36,-54.74)
N30693218: length 2.2
  TOP w0.135: LD3.3 174.81,-13.34 v1(174.83,-13.36)
  BOTTOM w0.135: R168.2 174.83,-12.04 v1(174.83,-13.36)
N30693408: length 2.8
  TOP w0.135: LD3.2 172.63,-13.34 v1(172.62,-13.33)
  BOTTOM w0.135: v1(172.62,-13.33) 173.09,-13.33 173.63,-12.8 R169.2
N30703604: length 1.3
  TOP w0.135: LD7.2 R86.2
N30811240: length 7.9
  TOP w0.135: LD3.4 174.76,-11.74 175.34,-12.32 175.34,-14.29 v1(175.58,-14.53)
  BOTTOM w0.135: Q9.2 Q9.1 176.23,-16.5 175.9,-16.18 Q9.8 176.23,-15.8 Q9.6 Q9.5 v1(175.58,-14.53)
N30811389: length 5.6
  TOP w0.135: LD3.1 173.27,-11.02 v1(172.81,-10.56)
  BOTTOM w0.135: Q4.5 Q4.6 ; Q4.6 v1(172.81,-10.56) ; Q4.6 172.06,-11.21 Q4.8 172.06,-11.86 Q4.1 Q4.2
N30900913: length 6.5
  TOP w0.102: 76.05,-41.82 U18.A15
  TOP w0.135: 76.05,-41.82 72.88,-41.82 v1(72.7,-41.64)
  BOTTOM w0.135: R240.1 72.7,-39.6 R244.1 72.7,-40.95 v1(72.7,-41.64)
N30979572: length 1.8
  TOP w0.135: U25.4 70.04,-58.23 70.31,-58.5 R162.2
N31410611: length 1.3
  TOP w0.135: R91.2 LD8.2
N31410626: length 4.8
  TOP w0.135: Q3.6 Q3.5 ; Q3.6 1.71,-39.93 Q3.8 1.71,-40.58 Q3.1 Q3.2 ; Q3.6 1.71,-38.78 1.72,-38.78 LD8.1
N31458583: length 2.4
  TOP w0.135: R119.2 13.59,-47.96 13.39,-47.75 13.39,-47.28 13,-46.89 U20.3
N31483389: length 1.3
  TOP w0.254: LD9.2 R94.2
N32041451: length 3.1
  TOP w0.254: U5.4 58.48,-25.13 58.05,-24.7 R31.2
N32341452: length 2.3
  TOP w0.135: v1(118.74,-49.84) 118.7,-49.84 118.78,-49.92 LD17.2
  BOTTOM w0.135: U52.7 118.89,-50.09 118.69,-49.89 118.69,-49.84 v1(118.74,-49.84)
N32341704: length 4
  BOTTOM w0.135: U52.8 119.29,-50.19 119.3,-50.17 119.31,-50.16 119.53,-49.94 R599.1
N32341897: length 3.5
  BOTTOM w0.135: U52.9 120.07,-51.47 120.64,-50.9 121.98,-50.9 122.52,-51.43 R600.1

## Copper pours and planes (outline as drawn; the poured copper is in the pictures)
DGND on BOTTOM (solid shape): 92.36,-18.87 92.41,-18.97 92.41,-19.74 92.44,-19.88 92.52,-20 94.27,-21.74 94.39,-21.82 94.53,-21.85 98.34,-21.85 98.99,-22.5 99.01,-22.61 98.91,-22.67 98.1,-22.67 98.04,-22.68 97.97,-22.7 97.39,-22.7 97.39,-22.56 97.36,-22.39 97.26,-22.25 97.26,-22.25 97.12,-22.16 96.95,-22.12 96.65,-22.25 96.52,-22.56 96.52,-22.8 96.52,-22.81 96.49,-22.88 96.49,-22.95 96.49,-23.31 96.58,-23.52 96.79,-23.61 97.12,-23.61 97.21,-23.6 97.29,-23.56 97.79,-23.56 97.79,-23.76 97.67,-23.79 97.57,-23.86 96.19,-23.86 91.92,-19.59 91.92,-19.07 92.09,-19 92.25,-18.89
DGND on BOTTOM (solid shape): 9.66,-12.8 9.69,-12.72 9.77,-12.7 9.81,-12.7 10.03,-12.7 10.06,-12.73 10.06,-13.05 10.06,-13.09 10.07,-13.14 10.07,-13.8 10.09,-13.94 10.17,-14.06 10.71,-14.6 10.8,-14.66 10.9,-14.7 10.94,-14.71 10.94,-15.19 11.03,-15.4 11.24,-15.49 11.7,-15.49 11.73,-15.49 11.77,-15.49 12.78,-15.49 12.78,-15.84 12.87,-16.05 13.09,-16.14 13.55,-16.14 13.69,-16.11 13.8,-16.01 13.9,-16.01 13.94,-16.02 13.98,-16.02 14.05,-16.01 14.12,-15.99 14.21,-16 14.26,-16.09 14.26,-16.69 14.29,-16.83 14.37,-16.95 15.34,-17.92 15.32,-17.96 15.29,-18.03 15.28,-18.1 15.28,-18.9 15.13,-18.99 15.04,-19.14 14.22,-19.14 14.22,-18.14 14.22,-18.1 14.22,-18.06 13.84,-17.68 13.46,-18.06 13.46,-18.1 13.47,-18.14 13.47,-19.47 13.5,-19.61 13.58,-19.73 13.68,-19.84 13.52,-20 13.41,-20.02 13.35,-19.93 13.35,-19.51 12.63,-18.79 12.52,-18.79 12.5,-18.76 12.46,-18.68 12.4,-18.61 9.77,-15.98 9.77,-15.14 9.86,-15.03 9.9,-14.89 9.9,-14.33 9.88,-14.22 9.81,-14.12 9.88,-14.03 9.9,-13.91 9.9,-13.35 9.84,-13.18 9.69,-13.06 9.66,-13.05
DGND on BOTTOM (solid shape): 55.08,-18.99 55.14,-18.89 55.25,-18.91 55.59,-19.11 55.99,-19.18 56.37,-19.11 56.71,-18.92 56.82,-18.9 56.88,-18.99 56.88,-19.43 52.31,-23.99 52.27,-24.05 52.23,-24.12 52.21,-24.15 52.17,-24.15 52.11,-24.13 52.05,-24.13 51.67,-24.51 52.05,-24.89 52.09,-24.89 52.17,-24.91 52.21,-24.99 52.21,-25.3 52.17,-25.38 52.09,-25.4 52.05,-25.4 51.67,-25.78 52.05,-26.16 52.09,-26.16 52.17,-26.18 52.21,-26.26 52.21,-26.57 52.17,-26.65 52.09,-26.67 52.05,-26.67 51.67,-27.05 52.05,-27.43 52.09,-27.43 52.17,-27.45 52.21,-27.53 52.21,-33.65 50.56,-35.3 50.45,-35.32 50.38,-35.23 50.38,-27.43 50.44,-27.34 50.55,-27.35 50.66,-27.41 50.78,-27.43 51.16,-27.05 50.78,-26.67 50.66,-26.69 50.55,-26.75 50.44,-26.76 50.38,-26.67 50.38,-26.16 50.44,-26.07 50.55,-26.08 50.66,-26.14 50.78,-26.16 51.16,-25.78 50.78,-25.4 50.66,-25.42 50.55,-25.48 50.44,-25.49 50.38,-25.4 50.38,-24.82 50.47,-24.74 50.63,-24.86 50.78,-24.89 51.05,-24.78 51.16,-24.51 51.14,-24.38 51.07,-24.26 51.05,-24.19 51.08,-24.13 54.97,-20.23 55.06,-20.11 55.08,-19.96
DGND on BOTTOM (solid shape): outline of 377 points within 83.4,-22.67 93.2,-14.16
DGND on BOTTOM (solid shape): outline of 777 points within 38.17,-35.97 45.35,-14.28
DGND on BOTTOM (solid shape): outline of 1162 points within 103.32,-26.52 125.66,-13.08
DGND on BOTTOM (solid shape): outline of 2471 points within 137.33,-44.06 175.4,-18.03
DGND on BOTTOM (solid shape): outline of 2859 points within 82.49,-31.64 184.68,-10.16
DGND on BOTTOM (solid shape): outline of 4093 points within 1.09,-46.17 78.93,-10.16
DGND on L03_SIG1 (solid shape): 122.35,-35.93 122.45,-35.99 122.43,-36.1 122.02,-36.51 121.94,-36.62 121.91,-36.76 121.91,-37.81 121.52,-38.2 121.41,-38.22 121.35,-38.13 121.35,-36.65 122.07,-35.93
DGND on L03_SIG1 (solid shape): 33.82,-15.95 33.89,-15.98 33.92,-16.06 33.92,-16.08 33.95,-16.23 34.03,-16.35 34.06,-16.46 33.96,-16.53 31.72,-16.53 31.58,-16.55 31.47,-16.63 30.91,-17.19 28.18,-17.19 28.08,-17.13 28.11,-17.02 29.17,-15.95
DGND on L03_SIG1 (solid shape): 45.61,-31.27 45.73,-31.35 45.87,-31.38 54.18,-31.38 54.57,-31.77 54.59,-31.88 54.5,-31.94 39.56,-31.94 38.93,-31.32 38.91,-31.21 39.01,-31.15 39.04,-31.15 41.64,-31.15 41.78,-31.12 41.9,-31.04 42.03,-30.92 42.12,-30.89 42.19,-30.95 42.33,-31.13 42.55,-31.19 42.81,-31.08 42.96,-30.75 43.03,-30.72 45.06,-30.72
DGND on L03_SIG1 (solid shape): 62.48,-35.81 62.56,-35.77 62.59,-35.77 64.46,-35.77 64.53,-35.8 64.56,-35.88 64.56,-35.89 64.67,-36.16 64.94,-36.27 65.07,-36.24 65.18,-36.18 65.25,-36.15 65.32,-36.18 65.55,-36.41 65.55,-38.4 65.54,-38.45 65.53,-38.51 65.53,-38.54 65.51,-38.62 65.43,-38.65 65.06,-38.65 63.24,-36.83 63.12,-36.75 62.98,-36.72 62.39,-36.72 62.16,-36.5 62.13,-36.4 62.2,-36.33 62.39,-36.19 62.46,-35.97 62.46,-35.93 62.45,-35.89
DGND on L03_SIG1 (solid shape): 184.68,-43.33 183.72,-43.33 183.63,-43.28 183.64,-43.17 183.79,-42.88 183.84,-42.56 183.53,-41.81 182.79,-41.5 182.25,-41.65 181.86,-42.05 181.77,-42.11 181.68,-42.05 181.29,-41.65 180.75,-41.5 180.68,-41.5 180.62,-41.51 180.53,-41.49 180.5,-41.41 180.5,-40.35 179.39,-39.24 179.4,-39.21 179.42,-39.14 179.43,-39.07 179.32,-38.8 179.05,-38.69 179.02,-38.69 178.92,-38.63 178.94,-38.52 182.34,-35.11 182.38,-35.13 182.58,-35.19 182.79,-35.21 183.29,-35.08 183.67,-34.73 184.68,-34.73
DGND on L03_SIG1 (solid shape): 37.75,-29.41 37.78,-29.48 37.76,-29.55 37.69,-29.66 37.67,-29.79 37.72,-29.99 37.87,-30.13 38,-30.26 38.02,-30.38 37.93,-30.44 37.91,-30.44 37.64,-30.55 37.53,-30.82 37.59,-31.01 37.73,-31.15 39.15,-32.57 39.26,-32.65 39.4,-32.67 54.89,-32.67 56.56,-34.35 56.68,-34.43 56.82,-34.45 61.12,-34.45 62.08,-35.42 62.1,-35.52 62.02,-35.59 61.83,-35.68 61.71,-35.86 61.65,-35.93 61.56,-35.92 61.48,-35.89 61.39,-35.88 57.99,-35.88 57.85,-35.91 57.73,-35.99 57.1,-36.62 56.99,-36.64 56.93,-36.55 56.93,-35.56 56.89,-35.4 56.8,-35.26 55.27,-33.73 55.13,-33.64 54.97,-33.6 39.63,-33.6 36.98,-30.96 36.84,-30.87 36.68,-30.84 35.69,-30.84 34.3,-29.45 34.27,-29.34 34.37,-29.27 35.48,-29.27 35.67,-29.24 35.83,-29.13 36.29,-28.67 37.01,-28.67
DGND on L03_SIG1 (solid shape): 36.06,-17.66 36.06,-18.72 35.79,-18.99 35.68,-19.01 35.62,-18.92 35.62,-18.44 35.59,-18.3 35.51,-18.18 35.21,-17.88 35.21,-17.87 35.07,-17.73 34.87,-17.68 34.6,-17.79 34.49,-18.06 34.55,-18.25 34.69,-18.39 34.69,-18.39 34.89,-18.59 34.89,-21.01 34.86,-21.08 34.79,-21.11 34.77,-21.11 34.5,-21.22 34.39,-21.49 34.42,-21.63 34.5,-21.76 34.53,-21.83 34.5,-21.9 33.26,-23.15 33.15,-23.17 33.08,-23.08 33.08,-21.85 33.14,-21.76 33.25,-21.77 33.37,-21.85 33.5,-21.87 33.88,-21.49 33.5,-21.11 33.37,-21.13 33.25,-21.2 33.14,-21.22 33.08,-21.13 33.08,-17.98 32.94,-17.63 32.59,-17.49 31.89,-17.49 31.8,-17.42 31.82,-17.31 31.88,-17.26 35.66,-17.26
DGND on L03_SIG1 (solid shape): 94.73,-25.91 94.82,-25.97 94.85,-26.02 94.89,-26.06 95.9,-27.08 95.9,-27.68 95.87,-27.75 95.54,-27.89 95.43,-28.16 95.54,-28.43 95.81,-28.54 95.95,-28.52 96.07,-28.44 96.14,-28.41 96.21,-28.44 96.25,-28.47 96.28,-28.54 96.25,-28.61 96.23,-28.64 96.21,-28.67 95.97,-28.91 95.5,-28.91 95.43,-28.89 95.28,-28.57 95.02,-28.47 94.97,-28.48 94.91,-28.49 94.71,-28.49 94.62,-28.44 94.62,-28.34 94.65,-28.25 94.67,-28.16 94.28,-27.78 93.9,-28.16 93.92,-28.25 93.95,-28.34 93.95,-28.44 93.86,-28.49 93.54,-28.49 92.67,-27.62 92.63,-27.59 92.59,-27.56 92.53,-27.49 92.56,-27.4 92.98,-26.98 93.09,-26.96 93.16,-27.05 93.16,-27.5 93.15,-27.56 93.14,-27.61 93.52,-27.99 93.9,-27.61 93.9,-27.56 93.89,-27.5 93.89,-26.14 93.95,-26.05 94.06,-26.07 94.17,-26.14 94.31,-26.16 94.5,-26.11 94.64,-25.97
DGND on L03_SIG1 (solid shape): outline of 215 points within 25.41,-32.8 34.88,-26.01
DGND on L03_SIG1 (solid shape): outline of 212 points within 72.74,-28.41 77.87,-25.94
DGND on L03_SIG1 (solid shape): outline of 92 points within 136.92,-35.26 143.05,-23.92
DGND on L03_SIG1 (solid shape): outline of 304 points within 120.88,-27.93 130.87,-24.39
DGND on L03_SIG1 (solid shape): outline of 123 points within 130.2,-34.15 137.18,-30.3
DGND on L03_SIG1 (solid shape): outline of 360 points within 95.68,-30.64 109.64,-23.63
DGND on L03_SIG1 (solid shape): outline of 424 points within 39.07,-43.45 56.19,-35.16
DGND on L03_SIG1 (solid shape): outline of 608 points within 88.42,-41.16 103.14,-35.77
DGND on L03_SIG1 (solid shape): outline of 646 points within 42.9,-38.78 80.14,-29.79
DGND on L03_SIG1 (solid shape): outline of 762 points within 79.14,-19.19 101.12,-14.61
DGND on L03_SIG1 (solid shape): outline of 1068 points within 1.09,-47.96 78.93,-10.19
DGND on L03_SIG1 (solid shape): outline of 1727 points within 33.87,-23.84 84.49,-13.75
DGND on L03_SIG1 (solid shape): outline of 1875 points within 89.51,-21.53 146.57,-13.35
DGND on L03_SIG1 (solid shape): outline of 4894 points within 82.27,-66.57 184.68,-10.19
DGND on TOP: 48.74,-37.8 49.57,-37.8 50.14,-37.23 55.36,-37.23 55.5,-37.09 55.5,-36.77 55.32,-36.59 54.83,-36.59 54.82,-36.59 50.02,-36.59 49.53,-37.08 48.76,-37.08 48.67,-37.18 48.67,-37.72
DGND on TOP: 72.95,-34.81 72.95,-37.05 73.37,-37.46 74.78,-37.46 76.76,-39.45 77.06,-39.45 77.52,-38.99 77.52,-38.73 77.01,-38.23 76.71,-38.23 74.69,-36.21 74.26,-36.21 73.52,-35.47 73.52,-34.81
DGND on TOP: 184.68,-10.16 184.68,-66.57 1.09,-66.57 1.09,-10.16 ; 101 cut-outs
DGND on TOP: 110.72,-22.22 110.72,-28.37 120.09,-28.37 120.09,-22.22
DGND on TOP: 100.22,-19.34 97.99,-19.34 97.79,-19.14 97.79,-17.75 97.97,-17.58 100.2,-17.58 100.31,-17.69 100.31,-19.24
